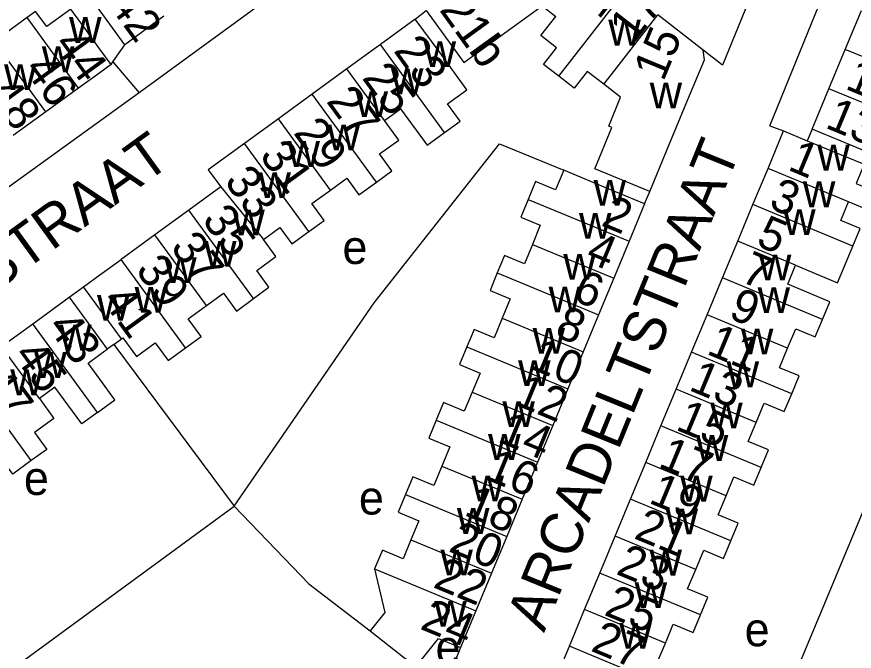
# Model space of a CAD drawing. Extents: x 159045 to 160918, y 380454 to 382516.
# Drawn here: x 159990.1 to 160089.8, y 381356.9 to 381432.4 of the extents above; entities that cross this region are included whole.
import ezdxf

# ---------------------------------------------------------------- set-up
doc = ezdxf.new("R2010")
doc.units = 0
for name, color, linetype in [('BLT_Basislijn', 7, 'Continuous'), ('BLT_Bebouwing', 7, 'Continuous'), ('BLT_Centroide', 7, 'Continuous'), ('BLT_Huisnummer', 7, 'Continuous'), ('BLT_Huisnummer_ tussenligend', 7, 'Continuous'), ('BLT_Huisnummer_reeks', 7, 'Continuous'), ('BLT_Onderdoorgang_en_onderverdeling', 7, 'Continuous'), ('BLT_Onderverdeling_panden', 7, 'Continuous'), ('BLT_Straatnaam', 7, 'Continuous')]:
    doc.layers.add(name, color=color, linetype=linetype)

msp = doc.modelspace()

# ---------------------------------------------------------------- linework, layer by layer
at = {"layer": 'BLT_Basislijn'}
for p, q in [((160037.568, 381432.172), (160038.859, 381433.197)), ((160001.568, 381427.065), (160002.971, 381429.116)), ((160001.349, 381426.745), (160001.568, 381427.065)), ((160001.568, 381427.065), (160004.68, 381423.379)), ((160004.68, 381423.379), (159972.842, 381400.42)), ((160079.788, 381419.45), (160081.421, 381418.845)), ((160084.812, 381419.054), (160084.234, 381417.676)), ((160064.863, 381410.165), (160065.483, 381411.617)), ((160001.669, 381393.412), (160016.007, 381374.121)), ((159981.714, 381349.046), (160016.007, 381374.121)), ((160042.959, 381357.286), (160040.921, 381352.366))]:
    msp.add_line(p, q, dxfattribs=at)
for points in [[(160053.686, 381442.564), (160050.986, 381444.6), (160072.32, 381460.498), (160072.532, 381462.878), (160073.892, 381464.068), (160076.357, 381464.409), (160078.652, 381463.303), (160085.123, 381458.011), (160085.902, 381457.192), (160086.27, 381456.28), (160082.215, 381446.443), (160074.141, 381426.657), (160071.859, 381428.467)], [(160079.788, 381419.45), (160087.885, 381439.374), (160090.066, 381444.678)], [(160026.831, 381439.559), (160025.633, 381438.694), (160004.68, 381423.379)], [(160016.007, 381374.121), (160032.652, 381398.345), (160047.59, 381417.311), (160055.238, 381414.152)], [(160073.348, 381331.438), (160073.582, 381332.011), (160091.811, 381375.741)], [(160016.007, 381374.121), (160024.881, 381364.887), (160032.195, 381359.288)]]:
    msp.add_lwpolyline(points, dxfattribs=at)
at = {"layer": 'BLT_Bebouwing'}
for p, q in [((160007.642, 381432.508), (160002.971, 381429.116)), ((160088.756, 381428.542), (160090.682, 381433.175)), ((160037.568, 381432.172), (160033.412, 381429.144)), ((160033.412, 381429.144), (160029.417, 381426.233)), ((160086.814, 381423.871), (160088.756, 381428.542)), ((160069.833, 381422.093), (160072.008, 381427.329)), ((160029.417, 381426.233), (160025.303, 381423.236)), ((159997.469, 381423.928), (159993.585, 381421.107)), ((160025.303, 381423.236), (160021.266, 381420.294)), ((160084.812, 381419.054), (160086.814, 381423.871)), ((160067.527, 381416.538), (160069.833, 381422.093)), ((159993.585, 381421.107), (159989.7, 381418.286)), ((160021.266, 381420.294), (160017.226, 381417.351)), ((160079.562, 381414.373), (160081.421, 381418.845)), ((160081.421, 381418.845), (160084.234, 381417.676)), ((160065.483, 381411.617), (160067.527, 381416.538)), ((160077.772, 381410.066), (160079.562, 381414.373)), ((160014.396, 381412.177), (160010.599, 381409.411)), ((160010.599, 381409.411), (160006.565, 381406.471)), ((160064.863, 381410.165), (160063.016, 381405.707)), ((160075.956, 381405.697), (160077.772, 381410.066)), ((160006.565, 381406.471), (160002.535, 381403.535)), ((160063.016, 381405.707), (160061.191, 381401.301)), ((160074.144, 381401.339), (160075.956, 381405.697)), ((160061.191, 381401.301), (160059.381, 381396.93)), ((160072.311, 381396.928), (160074.144, 381401.339)), ((159996.361, 381399.037), (159998.051, 381400.267)), ((159992.026, 381395.877), (159996.361, 381399.037)), ((160059.381, 381396.93), (160057.559, 381392.532)), ((160070.466, 381392.49), (160072.311, 381396.928)), ((159988.289, 381393.154), (159992.026, 381395.877)), ((160001.669, 381393.412), (160000.878, 381392.836)), ((160057.559, 381392.532), (160055.733, 381388.123)), ((160068.636, 381388.087), (160070.466, 381392.49)), ((160055.733, 381388.123), (160053.924, 381383.758)), ((160066.813, 381383.701), (160068.636, 381388.087)), ((160053.924, 381383.758), (160052.111, 381379.379)), ((160065.002, 381379.344), (160066.813, 381383.701)), ((160052.111, 381379.379), (160050.279, 381374.957)), ((160063.189, 381374.984), (160065.002, 381379.344)), ((160050.279, 381374.957), (160048.446, 381370.533)), ((160061.357, 381370.575), (160063.189, 381374.984)), ((160048.446, 381370.533), (160046.637, 381366.164)), ((160059.529, 381366.178), (160061.357, 381370.575)), ((160046.637, 381366.164), (160044.78, 381361.683)), ((160057.723, 381361.833), (160059.529, 381366.178)), ((160044.78, 381361.683), (160042.959, 381357.286)), ((160055.909, 381357.469), (160057.723, 381361.833)), ((160054.084, 381353.079), (160055.909, 381357.469))]:
    msp.add_line(p, q, dxfattribs=at)
for points in [[(160002.971, 381429.116), (160000.029, 381433.159), (159998.614, 381435.103), (159996.609, 381437.859), (160001.355, 381441.313)], [(159996.552, 381433.351), (159993.675, 381431.262), (159992.35, 381433.087), (159991.347, 381432.359)], [(160001.349, 381426.745), (160000.007, 381428.593), (159998.411, 381430.79), (159996.552, 381433.351)], [(160038.859, 381433.197), (160041.789, 381429.147), (160043.336, 381427.009), (160052.669, 381433.76), (160054.309, 381432.488)], [(159991.347, 381432.359), (159990.147, 381431.488), (159987.415, 381429.506)], [(160054.664, 381425.358), (160052.849, 381426.766), (160054.389, 381428.751), (160052.529, 381430.193), (160054.309, 381432.488)], [(160071.859, 381428.467), (160066.439, 381432.672)], [(160043.7, 381423.756), (160040.513, 381428.131), (160037.568, 381432.172)], [(160072.008, 381427.329), (160071.859, 381428.467)], [(160001.349, 381426.745), (160000, 381425.766), (159997.469, 381423.928)], [(160060.018, 381424.392), (160058.022, 381425.94), (160056.479, 381423.95), (160054.664, 381425.358)], [(160060.981, 381419.257), (160060.592, 381419.418), (160062.014, 381422.844), (160060.018, 381424.392)], [(160041.06, 381418.647), (160042.914, 381419.998), (160041.398, 381422.079), (160043.7, 381423.756)], [(160033.9, 381420.079), (160035.812, 381421.472), (160038.977, 381417.129), (160041.06, 381418.647)], [(160032.946, 381412.747), (160034.776, 381414.081), (160033.308, 381416.095), (160035.591, 381417.758), (160033.9, 381420.079)], [(160058.937, 381414.335), (160060.981, 381419.257)], [(160094.422, 381415.059), (160089.429, 381417.135), (160084.812, 381419.054)], [(160017.226, 381417.351), (160012.915, 381414.21), (160014.396, 381412.177)], [(160084.234, 381417.676), (160086.038, 381416.926), (160090.993, 381414.866), (160090.039, 381412.571), (160092.415, 381411.584), (160091.509, 381409.405), (160089.137, 381410.391)], [(160065.483, 381411.617), (160058.937, 381414.335)], [(160055.238, 381414.152), (160054.271, 381411.817), (160051.881, 381412.807), (160051.002, 381410.685)], [(160064.863, 381410.165), (160060.244, 381412.078), (160055.238, 381414.152)], [(160027.463, 381411.787), (160029.403, 381413.201), (160030.848, 381411.218), (160032.946, 381412.747)], [(160024.879, 381406.848), (160026.709, 381408.182), (160025.254, 381410.178), (160027.463, 381411.787)], [(160051.002, 381410.685), (160050.123, 381408.564), (160052.453, 381407.599), (160051.506, 381405.312)], [(160089.679, 381405.114), (160090.554, 381407.218), (160088.221, 381408.188), (160089.137, 381410.391)], [(160019.489, 381405.902), (160021.44, 381407.324), (160022.859, 381405.376), (160024.879, 381406.848)], [(160018.285, 381398.862), (160020.141, 381400.214), (160018.682, 381402.217), (160020.963, 381403.879), (160019.489, 381405.902)], [(160051.506, 381405.312), (160050.559, 381403.026), (160048.19, 381404.007), (160047.326, 381401.922)], [(160082.846, 381402.832), (160087.853, 381400.731), (160088.804, 381403.01), (160089.679, 381405.114)], [(159998.051, 381400.267), (160000, 381401.687), (160002.535, 381403.535)], [(160086.034, 381396.395), (160086.906, 381398.492), (160081.906, 381400.57), (160082.846, 381402.832)], [(160047.326, 381401.922), (160046.463, 381399.837), (160048.88, 381398.835), (160047.922, 381396.523)], [(160012.698, 381398.053), (160014.713, 381399.522), (160016.266, 381397.39), (160018.285, 381398.862)], [(160010.216, 381392.997), (160012.064, 381394.344), (160010.519, 381396.466), (160012.698, 381398.053)], [(160047.922, 381396.523), (160046.965, 381394.212), (160044.572, 381395.204), (160043.703, 381393.108)], [(160081.896, 381392.943), (160082.858, 381395.257), (160085.163, 381394.299), (160086.034, 381396.395)], [(160001.669, 381393.412), (160002.568, 381394.067)], [(160002.568, 381394.067), (160002.758, 381394.205), (160004.379, 381391.98)], [(160004.379, 381391.98), (160006.609, 381393.605), (160008.148, 381391.491), (160010.216, 381392.997)], [(159999.73, 381385.303), (160001.8, 381386.811), (160000.011, 381389.267), (159998.613, 381391.185), (160000.008, 381392.202), (160000.878, 381392.836)], [(160043.703, 381393.108), (160042.835, 381391.012), (160045.271, 381390.002), (160044.33, 381387.731)], [(160082.384, 381387.537), (160083.266, 381389.659), (160080.934, 381390.629), (160081.896, 381392.943)], [(159999.73, 381385.303), (159997.844, 381383.93), (159994.654, 381388.308), (159992.802, 381386.96)], [(160044.33, 381387.731), (160043.39, 381385.46), (160040.932, 381386.479), (160040.058, 381384.369)], [(160078.163, 381384.127), (160079.112, 381386.409), (160081.502, 381385.415), (160082.384, 381387.537)], [(159992.802, 381386.96), (159994.535, 381384.582), (159992.235, 381382.906), (159993.692, 381380.906), (159991.848, 381379.562)], [(160040.058, 381384.369), (160039.185, 381382.26), (160041.694, 381381.221), (160040.736, 381378.909)], [(160078.747, 381378.74), (160079.622, 381380.844), (160077.215, 381381.845), (160078.163, 381384.127)], [(159991.848, 381379.562), (159989.643, 381377.956), (159988.169, 381379.98), (159986.217, 381378.558), (159984.692, 381380.652)], [(160040.736, 381378.909), (160039.779, 381376.597), (160037.274, 381377.634), (160036.399, 381375.522)], [(160074.573, 381375.366), (160075.51, 381377.619), (160077.873, 381376.636), (160078.747, 381378.74)], [(160036.399, 381375.522), (160035.525, 381373.411), (160037.987, 381372.392), (160037.052, 381370.135)], [(160075.146, 381370.014), (160076.022, 381372.122), (160073.637, 381373.113), (160074.573, 381375.366)], [(160037.052, 381370.135), (160036.117, 381367.879), (160033.645, 381368.903), (160032.723, 381366.677)], [(160070.952, 381366.586), (160071.909, 381368.888), (160074.27, 381367.907), (160075.146, 381370.014)], [(160032.723, 381366.677), (160033.929, 381361.488), (160032.195, 381359.288)], [(160071.507, 381361.198), (160072.378, 381363.293), (160069.995, 381364.284), (160070.952, 381366.586)], [(160067.343, 381357.834), (160068.278, 381360.084), (160070.636, 381359.103), (160071.507, 381361.198)], [(160032.195, 381359.288), (160033.713, 381358.092), (160037.639, 381354.996)], [(160037.639, 381354.996), (160040.309, 381358.383), (160042.959, 381357.286)], [(160067.851, 381352.503), (160068.731, 381354.619), (160066.408, 381355.585), (160067.343, 381357.834)]]:
    msp.add_lwpolyline(points, dxfattribs=at)
at = {"layer": 'BLT_Onderdoorgang_en_onderverdeling'}
for p, q in [((160002.568, 381394.067), (159998.051, 381400.267)), ((159996.361, 381399.037), (160000.878, 381392.836))]:
    msp.add_line(p, q, dxfattribs=at)
at = {"layer": 'BLT_Onderverdeling_panden'}
for p, q in [((160054.664, 381425.358), (160062.63, 381435.626)), ((159997.469, 381423.928), (159991.347, 381432.359)), ((160061.06, 381425.736), (160066.439, 381432.672)), ((159993.585, 381421.107), (159987.415, 381429.506)), ((160041.06, 381418.647), (160033.412, 381429.144)), ((160097.877, 381424.75), (160088.756, 381428.542)), ((160033.9, 381420.079), (160029.417, 381426.233)), ((160060.018, 381424.392), (160061.06, 381425.736)), ((160032.946, 381412.747), (160025.303, 381423.236)), ((160099.058, 381418.781), (160086.814, 381423.871)), ((160027.463, 381411.787), (160021.266, 381420.294)), ((160024.879, 381406.848), (160017.226, 381417.351)), ((160089.137, 381410.391), (160079.562, 381414.373)), ((160014.396, 381412.177), (160019.489, 381405.902)), ((160051.002, 381410.685), (160063.016, 381405.707)), ((160018.285, 381398.862), (160010.599, 381409.411)), ((160089.679, 381405.114), (160077.772, 381410.066)), ((160012.698, 381398.053), (160006.565, 381406.471)), ((160051.506, 381405.312), (160061.191, 381401.301)), ((160082.846, 381402.832), (160075.956, 381405.697)), ((160010.216, 381392.997), (160002.535, 381403.535)), ((160047.326, 381401.922), (160059.381, 381396.93)), ((160086.034, 381396.395), (160074.144, 381401.339)), ((160047.922, 381396.523), (160057.559, 381392.532)), ((160081.896, 381392.943), (160072.311, 381396.928)), ((159999.73, 381385.303), (159992.026, 381395.877)), ((159992.802, 381386.96), (159988.289, 381393.154)), ((160043.703, 381393.108), (160055.733, 381388.123)), ((160082.384, 381387.537), (160070.466, 381392.49)), ((159991.848, 381379.562), (159984.145, 381390.135)), ((160044.33, 381387.731), (160053.924, 381383.758)), ((160078.163, 381384.127), (160068.636, 381388.087)), ((160040.058, 381384.369), (160052.111, 381379.379)), ((160078.747, 381378.74), (160066.813, 381383.701)), ((160074.573, 381375.366), (160065.002, 381379.344)), ((160040.736, 381378.909), (160050.279, 381374.957)), ((160036.399, 381375.522), (160048.446, 381370.533)), ((160075.146, 381370.014), (160063.189, 381374.984)), ((160070.952, 381366.586), (160061.357, 381370.575)), ((160037.052, 381370.135), (160046.637, 381366.164)), ((160032.723, 381366.677), (160044.78, 381361.683)), ((160071.507, 381361.198), (160059.529, 381366.178)), ((160067.343, 381357.834), (160057.723, 381361.833)), ((160067.851, 381352.503), (160055.909, 381357.469))]:
    msp.add_line(p, q, dxfattribs=at)

# ---------------------------------------------------------------- texts
at = {"layer": 'BLT_Centroide'}
for s, p in [('w', (159996.344, 381429.328)), ('w', (160060.547, 381429.016)), ('w', (160038.562, 381426.453)), ('w', (159993.109, 381425.828)), ('w', (159988.594, 381423.719)), ('w', (160034.672, 381423.219)), ('w', (160065.469, 381421.531)), ('w', (160030.453, 381420.5)), ('w', (160027.109, 381416.516)), ('w', (160022.344, 381414.562)), ('w', (160085.422, 381414.125)), ('w', (160018.891, 381410.844)), ('w', (160058.797, 381409.938)), ('w', (160083.711, 381409.75)), ('w', (160015.781, 381406.391)), ('w', (160081.367, 381406.438)), ('w', (160057.055, 381406)), ('w', (160012.422, 381402.672)), ('e', (160028.893, 381402.992)), ('w', (160007.672, 381400.719)), ('w', (160055.188, 381401.125)), ('w', (160078.477, 381401.031)), ('w', (160053.438, 381397.219)), ('w', (159999.672, 381396.233)), ('w', (160004.141, 381397.188)), ('w', (160078.32, 381397.156)), ('w', (159995.161, 381392.679)), ('w', (160051.531, 381392.312)), ('w', (160076.336, 381392.219)), ('w', (159992.191, 381389.425)), ('w', (160049.805, 381388.438)), ('w', (160074.633, 381388.312)), ('w', (159989.344, 381387.359)), ('w', (160047.938, 381383.562)), ('w', (160072.68, 381383.406)), ('w', (160046.234, 381379.656)), ('w', (160070.961, 381379.531)), ('e', (159990.964, 381375.48)), ('w', (160044.258, 381374.719)), ('w', (160069.102, 381374.688)), ('e', (160030.849, 381373.146)), ('w', (160042.523, 381370.844)), ('w', (160067.367, 381370.781)), ('w', (160040.555, 381365.906)), ('w', (160065.445, 381365.875)), ('w', (160063.68, 381362)), ('w', (160039.828, 381359.781)), ('e', (160076.777, 381357.455)), ('w', (160061.852, 381357.156)), ('e', (160039.972, 381355.358))]:
    msp.add_text(s, height=4, dxfattribs=at).set_placement(p)
at = {"layer": 'BLT_Huisnummer'}
for s, rotation, p in [('19', 52.20703, (160059.415, 381432.013)), ('17', 52.20703, (160063.55, 381429.147)), ('15', 67.44749, (160067.095, 381424.625)), ('44', 306.0358, (159994.414, 381429.126)), ('23', 306.07668, (160034.891, 381428.392)), ('48', 305.98355, (159986.487, 381423.409)), ('27', 306.07963, (160026.887, 381422.369)), ('13', 337.43038, (160086.239, 381419.272)), ('31', 306.07891, (160018.917, 381415.889)), ('1', 337.41881, (160081.783, 381414.259)), ('2', 337.50333, (160059.564, 381407.613)), ('35', 306.07464, (160012.079, 381408.227)), ('5', 337.42189, (160077.996, 381405.243)), ('39', 306.07575, (160004.167, 381402.267)), ('6', 337.50546, (160056.147, 381398.75)), ('9', 337.43273, (160074.719, 381396.608)), ('43', 306.07739, (159993.663, 381395.516)), ('10', 337.50492, (160050.96, 381390.635)), ('13', 337.42926, (160070, 381388.012)), ('47', 306.07411, (159985.623, 381388.857)), ('14', 337.51021, (160047.233, 381381.876)), ('17', 337.42148, (160066.361, 381378.876)), ('18', 337.50418, (160043.234, 381373.127)), ('21', 337.42472, (160063.464, 381370.355)), ('25', 337.42719, (160059.909, 381361.229)), ('24', 337.51229, (160037.999, 381359.567))]:
    msp.add_text(s, height=4, rotation=rotation, dxfattribs=at).set_placement(p)
at = {"layer": 'BLT_Huisnummer_ tussenligend'}
for s, rotation, p in [('42', 305.99104, (160000.922, 381433.925)), ('46', 306.0358, (159990.885, 381426.186)), ('25', 306.07668, (160031.141, 381425.151)), ('11', 337.4252, (160088.617, 381423.908)), ('29', 306.07963, (160022.971, 381418.609)), ('33', 306.07891, (160014.732, 381412.841)), ('3', 337.41881, (160079.513, 381409.717)), ('37', 306.07464, (160008.32, 381404.997)), ('4', 337.50333, (160057.696, 381403.332)), ('7', 337.42189, (160076.128, 381400.963)), ('41', 306.07575, (160000.173, 381398.657)), ('8', 337.50546, (160054.012, 381394.461)), ('11', 337.43273, (160072.103, 381392.323)), ('45', 306.07739, (159989.622, 381392.095)), ('12', 337.50492, (160049.116, 381386.344)), ('15', 337.42926, (160068.43, 381383.298)), ('16', 337.51021, (160045.665, 381377.447)), ('19', 337.42148, (160065.227, 381374.587)), ('20', 337.50418, (160041.39, 381368.812)), ('23', 337.42472, (160061.336, 381366.099)), ('22', 337.50418, (160039.547, 381364.521)), ('27', 337.42719, (160058.325, 381356.949))]:
    msp.add_text(s, height=4, rotation=rotation, dxfattribs=at).set_placement(p)
at = {"layer": 'BLT_Huisnummer_reeks'}
msp.add_text('21b', height=4, rotation=305.88411, dxfattribs=at).set_placement((160040.349, 381433.264))
at = {"layer": 'BLT_Straatnaam'}
for s, rotation, p in [('LASSUSSTRAAT', 35.93581, (159965.996, 381383.991)), ('ARCADELTSTRAAT', 67.83512, (160052.891, 381359.006))]:
    msp.add_text(s, height=5, rotation=rotation, dxfattribs=at).set_placement(p)

doc.saveas('drawing.dxf')
